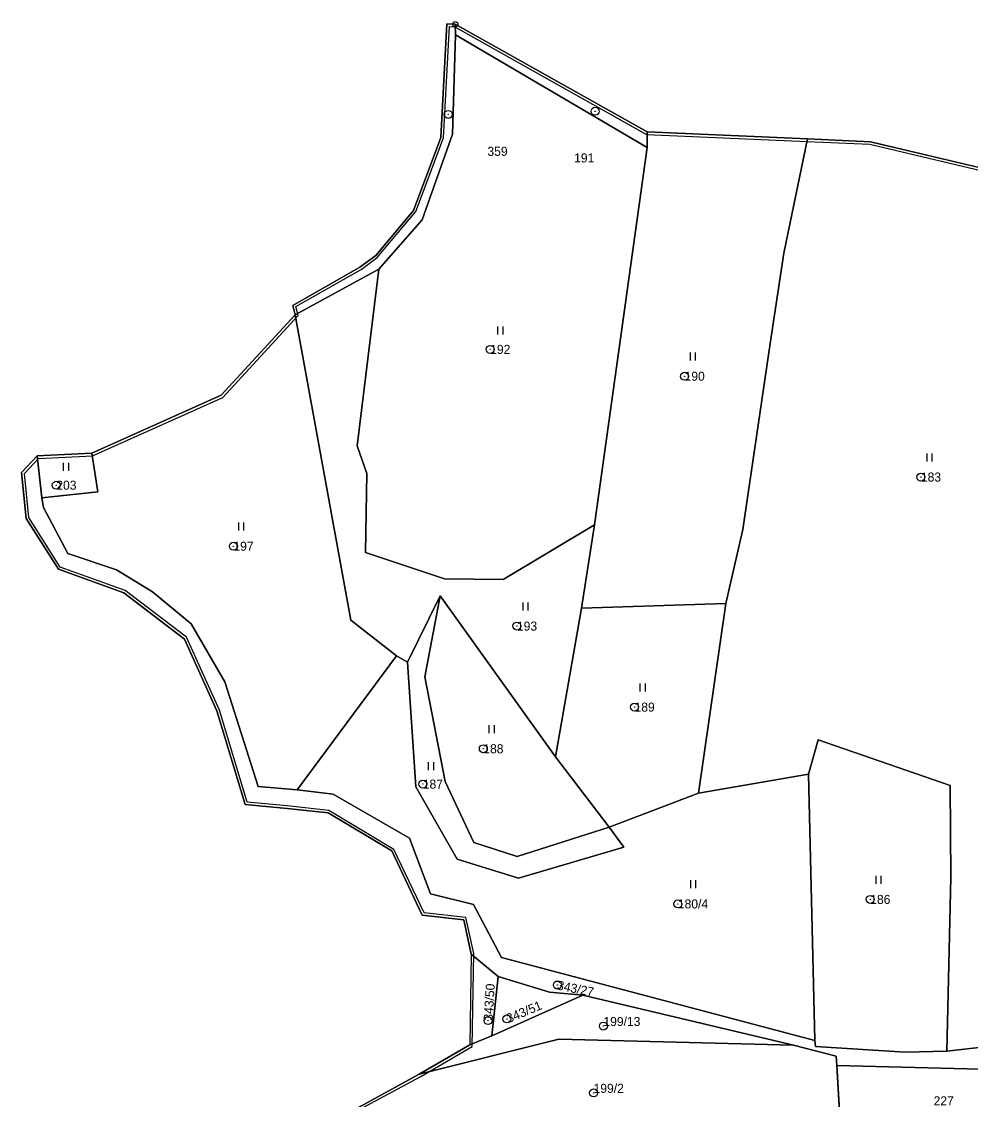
# Model space of a CAD drawing. Extents: x -652854 to -650068, y -1097661 to -1095417.
# Drawn here: x -651244.8 to -651066.4, y -1095861.8 to -1095659.2 of the extents above; entities that cross this region are included whole.
import ezdxf

# ---------------------------------------------------------------- set-up
doc = ezdxf.new("R2010")
doc.units = 0
for name, color, linetype in [('Definiční body parcel', 7, 'Continuous'), ('Geodetické body', 7, 'Continuous'), ('Hranice obcí', 7, 'Continuous'), ('Hranice parcel', 7, 'Continuous'), ('Obvody jako plochy', 7, 'Continuous'), ('Ostatní hranice', 7, 'Continuous'), ('Parcelní čísla', 7, 'Continuous'), ('Prvky pro prodl_ par_ č_', 7, 'Continuous'), ('Značky kultur', 7, 'Continuous')]:
    doc.layers.add(name, color=color, linetype=linetype)

msp = doc.modelspace()

# ---------------------------------------------------------------- linework, layer by layer
at = {"layer": 'Definiční body parcel'}
for centre, radius in [((-651164.58, -1095676.69), 0.75), ((-651164.58, -1095676.69), 0.0327), ((-651136.98, -1095676.09), 0.75), ((-651136.98, -1095676.09), 0.0327), ((-651156.7, -1095720.83), 0.75), ((-651156.7, -1095720.83), 0.0327), ((-651120.17, -1095725.88), 0.75), ((-651120.17, -1095725.88), 0.0327), ((-651075.76, -1095744.82), 0.75), ((-651238.24, -1095746.35), 0.75), ((-651075.76, -1095744.82), 0.0327), ((-651238.24, -1095746.35), 0.0327), ((-651204.96, -1095757.82), 0.75), ((-651204.96, -1095757.82), 0.0327), ((-651151.67, -1095772.83), 0.75), ((-651151.67, -1095772.83), 0.0327), ((-651129.57, -1095788.05), 0.75), ((-651129.57, -1095788.05), 0.0327), ((-651157.99, -1095795.88), 0.75), ((-651157.99, -1095795.88), 0.0327), ((-651169.36, -1095802.52), 0.75), ((-651169.36, -1095802.52), 0.0327), ((-651121.43, -1095825.03), 0.75), ((-651121.43, -1095825.03), 0.0327), ((-651085.28, -1095824.19), 0.75), ((-651085.28, -1095824.19), 0.0327), ((-651144.06, -1095840.27), 0.75), ((-651144.06, -1095840.27), 0.0327), ((-651157.1, -1095846.95), 0.75), ((-651157.1, -1095846.95), 0.0327), ((-651153.55, -1095846.64), 0.75), ((-651153.55, -1095846.64), 0.0327), ((-651135.42, -1095847.98), 0.75), ((-651135.42, -1095847.98), 0.0327), ((-651137.27, -1095860.54), 0.75), ((-651137.27, -1095860.54), 0.0327)]:
    msp.add_circle(centre, radius, dxfattribs=at)
at = {"layer": 'Geodetické body'}
for radius in [0.5, 0.001]:
    msp.add_circle((-651163.27, -1095659.73), radius, dxfattribs=at)
at = {"layer": 'Hranice obcí'}
for p, q in [((-651165.95, -1095681.01), (-651164.84, -1095659.68)), ((-651164.84, -1095659.68), (-651163.27, -1095659.73)), ((-651163.27, -1095659.73), (-651127.2, -1095679.95)), ((-651171.1, -1095694.72), (-651165.95, -1095681.01)), ((-651127.2, -1095679.95), (-651097.08, -1095681.29)), ((-651097.08, -1095681.29), (-651085.24, -1095681.81)), ((-651085.24, -1095681.81), (-651060.33, -1095687.71)), ((-651178.22, -1095703.17), (-651171.1, -1095694.72)), ((-651181.22, -1095705.41), (-651178.22, -1095703.17)), ((-651193.76, -1095712.57), (-651181.22, -1095705.41)), ((-651193.34, -1095714.35), (-651193.76, -1095712.57)), ((-651207.25, -1095729.45), (-651193.34, -1095714.35)), ((-651231.54, -1095740.33), (-651207.25, -1095729.45)), ((-651244.77, -1095743.96), (-651241.84, -1095740.85)), ((-651241.84, -1095740.85), (-651231.54, -1095740.33)), ((-651243.9, -1095752.59), (-651244.77, -1095743.96)), ((-651237.83, -1095762.16), (-651243.9, -1095752.59)), ((-651225.54, -1095766.59), (-651237.83, -1095762.16)), ((-651214.13, -1095775.29), (-651225.54, -1095766.59)), ((-651208.05, -1095788.78), (-651214.13, -1095775.29)), ((-651202.75, -1095806.38), (-651208.05, -1095788.78)), ((-651194.85, -1095807.11), (-651202.75, -1095806.38)), ((-651187.17, -1095807.94), (-651194.85, -1095807.11)), ((-651175.2, -1095815.09), (-651187.17, -1095807.94)), ((-651169.48, -1095827.15), (-651175.2, -1095815.09)), ((-651161.68, -1095828.05), (-651169.48, -1095827.15)), ((-651160.28, -1095834.46), (-651161.68, -1095828.05)), ((-651160.28, -1095834.46), (-651160.53, -1095851.53)), ((-651170.03, -1095857.03), (-651160.53, -1095851.53)), ((-651182.24, -1095863.72), (-651170.03, -1095857.03))]:
    msp.add_line(p, q, dxfattribs=at)
at = {"layer": 'Hranice parcel'}
for p, q in [((-651163.27, -1095659.73), (-651163.25, -1095661.73)), ((-651163.25, -1095661.73), (-651163.78, -1095680.37)), ((-651163.25, -1095661.73), (-651127.23, -1095682.88)), ((-651163.78, -1095680.37), (-651169.48, -1095696.47)), ((-651127.23, -1095682.88), (-651127.2, -1095679.95)), ((-651101.52, -1095702.76), (-651097.08, -1095681.29)), ((-651127.23, -1095682.88), (-651137.08, -1095753.83)), ((-651169.48, -1095696.47), (-651177.62, -1095705.76)), ((-651104.09, -1095719.7), (-651101.52, -1095702.76)), ((-651177.62, -1095705.76), (-651193.34, -1095714.35)), ((-651177.62, -1095705.76), (-651181.69, -1095738.94)), ((-651193.34, -1095714.35), (-651182.87, -1095771.73)), ((-651109.22, -1095754.65), (-651104.09, -1095719.7)), ((-651181.69, -1095738.94), (-651179.89, -1095744.15)), ((-651241.84, -1095740.85), (-651240.93, -1095748.75)), ((-651230.42, -1095747.57), (-651231.54, -1095740.33)), ((-651179.89, -1095744.15), (-651180.15, -1095759.02)), ((-651240.93, -1095748.75), (-651230.42, -1095747.57)), ((-651240.93, -1095748.75), (-651240.67, -1095750.53)), ((-651240.67, -1095750.53), (-651236.07, -1095759.2)), ((-651154.26, -1095764.1), (-651137.08, -1095753.83)), ((-651137.08, -1095753.83), (-651139.55, -1095769.48)), ((-651112.39, -1095768.57), (-651109.22, -1095754.65)), ((-651236.07, -1095759.2), (-651226.94, -1095762.27)), ((-651180.15, -1095759.02), (-651165.27, -1095763.93)), ((-651226.94, -1095762.27), (-651220.14, -1095766.41)), ((-651165.27, -1095763.93), (-651154.26, -1095764.1)), ((-651220.14, -1095766.41), (-651212.91, -1095772.43)), ((-651166.12, -1095767.15), (-651172.24, -1095779.58)), ((-651166.12, -1095767.15), (-651169.01, -1095782.37)), ((-651144.45, -1095797.37), (-651166.12, -1095767.15)), ((-651139.55, -1095769.48), (-651144.45, -1095797.37)), ((-651139.55, -1095769.48), (-651112.39, -1095768.57)), ((-651117.53, -1095804.25), (-651112.39, -1095768.57)), ((-651212.91, -1095772.43), (-651206.57, -1095783.31)), ((-651182.87, -1095771.73), (-651174.28, -1095778.39)), ((-651174.28, -1095778.39), (-651192.98, -1095803.61)), ((-651174.28, -1095778.39), (-651172.24, -1095779.58)), ((-651172.24, -1095779.58), (-651170.68, -1095803.06)), ((-651169.01, -1095782.37), (-651165.15, -1095802.04)), ((-651206.57, -1095783.31), (-651200.29, -1095802.99)), ((-651096.89, -1095800.65), (-651095.09, -1095794.17)), ((-651095.09, -1095794.17), (-651070.25, -1095802.81)), ((-651134.33, -1095810.62), (-651144.45, -1095797.37)), ((-651117.53, -1095804.25), (-651096.89, -1095800.65)), ((-651096.89, -1095800.65), (-651095.71, -1095850.7)), ((-651165.15, -1095802.04), (-651159.77, -1095813.5)), ((-651070.25, -1095802.81), (-651070.13, -1095820.09)), ((-651200.29, -1095802.99), (-651192.98, -1095803.61)), ((-651192.98, -1095803.61), (-651186.19, -1095804.38)), ((-651186.19, -1095804.38), (-651171.85, -1095812.66)), ((-651170.68, -1095803.06), (-651162.88, -1095816.62)), ((-651134.33, -1095810.62), (-651117.53, -1095804.25)), ((-651151.61, -1095816.14), (-651134.33, -1095810.62)), ((-651131.57, -1095814.34), (-651134.33, -1095810.62)), ((-651171.85, -1095812.66), (-651167.94, -1095823.12)), ((-651159.77, -1095813.5), (-651151.61, -1095816.14)), ((-651151.37, -1095820.22), (-651131.57, -1095814.34)), ((-651162.88, -1095816.62), (-651151.37, -1095820.22)), ((-651070.13, -1095820.09), (-651070.86, -1095852.7)), ((-651167.94, -1095823.12), (-651159.86, -1095825.12)), ((-651159.86, -1095825.12), (-651154.58, -1095835.1)), ((-651155.23, -1095838.66), (-651160.28, -1095834.46)), ((-651154.58, -1095835.1), (-651095.71, -1095850.7)), ((-651155.23, -1095838.66), (-651156.42, -1095849.83)), ((-651145.53, -1095841.59), (-651155.23, -1095838.66)), ((-651156.42, -1095849.83), (-651139.31, -1095842.16)), ((-651139.31, -1095842.16), (-651145.53, -1095841.59)), ((-651139.31, -1095842.16), (-651099.73, -1095851.59)), ((-651143.81, -1095850.45), (-651170.03, -1095857.03)), ((-651160.53, -1095851.53), (-651156.42, -1095849.83)), ((-651099.73, -1095851.59), (-651143.81, -1095850.45)), ((-651095.71, -1095850.7), (-651095.54, -1095851.8)), ((-651099.73, -1095851.59), (-651091.66, -1095853.64)), ((-651095.54, -1095851.8), (-651078.71, -1095852.88)), ((-651078.71, -1095852.88), (-651070.86, -1095852.7)), ((-651070.86, -1095852.7), (-651063.2, -1095851.8)), ((-651091.53, -1095855.39), (-651091.66, -1095853.64)), ((-651091.53, -1095855.39), (-651054.94, -1095856.32)), ((-651090.63, -1095871.34), (-651091.53, -1095855.39))]:
    msp.add_line(p, q, dxfattribs=at)
at = {"layer": 'Obvody jako plochy'}
for points in [[(-651163.78, -1095680.37), (-651163.25, -1095661.73), (-651163.27, -1095659.73), (-651164.84, -1095659.68), (-651165.95, -1095681.01), (-651171.1, -1095694.72), (-651178.22, -1095703.17), (-651181.22, -1095705.41), (-651193.76, -1095712.57), (-651193.34, -1095714.35), (-651177.62, -1095705.76), (-651169.48, -1095696.47)], [(-651163.25, -1095661.73), (-651127.23, -1095682.88), (-651127.2, -1095679.95), (-651163.27, -1095659.73)], [(-651163.78, -1095680.37), (-651169.48, -1095696.47), (-651177.62, -1095705.76), (-651181.69, -1095738.94), (-651179.89, -1095744.15), (-651180.15, -1095759.02), (-651165.27, -1095763.93), (-651154.26, -1095764.1), (-651137.08, -1095753.83), (-651127.23, -1095682.88), (-651163.25, -1095661.73)], [(-651112.39, -1095768.57), (-651109.22, -1095754.65), (-651104.09, -1095719.7), (-651101.52, -1095702.76), (-651097.08, -1095681.29), (-651127.2, -1095679.95), (-651127.23, -1095682.88), (-651137.08, -1095753.83), (-651139.55, -1095769.48)], [(-651112.39, -1095768.57), (-651117.53, -1095804.25), (-651096.89, -1095800.65), (-651095.09, -1095794.17), (-651070.25, -1095802.81), (-651070.13, -1095820.09), (-651070.86, -1095852.7), (-651063.2, -1095851.8), (-651060.77, -1095828.02), (-651058.73, -1095802.33), (-651055.01, -1095780.49), (-651049.97, -1095744.99), (-651047.21, -1095731.45), (-651038.08, -1095692.34), (-651060.33, -1095687.71), (-651085.24, -1095681.81), (-651097.08, -1095681.29), (-651101.52, -1095702.76), (-651104.09, -1095719.7), (-651109.22, -1095754.65)], [(-651177.62, -1095705.76), (-651193.34, -1095714.35), (-651182.87, -1095771.73), (-651174.28, -1095778.39), (-651172.24, -1095779.58), (-651166.12, -1095767.15), (-651144.45, -1095797.37), (-651139.55, -1095769.48), (-651137.08, -1095753.83), (-651154.26, -1095764.1), (-651165.27, -1095763.93), (-651180.15, -1095759.02), (-651179.89, -1095744.15), (-651181.69, -1095738.94)], [(-651207.25, -1095729.45), (-651231.54, -1095740.33), (-651230.42, -1095747.57), (-651240.93, -1095748.75), (-651240.67, -1095750.53), (-651236.07, -1095759.2), (-651226.94, -1095762.27), (-651220.14, -1095766.41), (-651212.91, -1095772.43), (-651206.57, -1095783.31), (-651200.29, -1095802.99), (-651192.98, -1095803.61), (-651174.28, -1095778.39), (-651182.87, -1095771.73), (-651193.34, -1095714.35)], [(-651241.84, -1095740.85), (-651240.93, -1095748.75), (-651230.42, -1095747.57), (-651231.54, -1095740.33)], [(-651172.24, -1095779.58), (-651170.68, -1095803.06), (-651162.88, -1095816.62), (-651151.37, -1095820.22), (-651131.57, -1095814.34), (-651134.33, -1095810.62), (-651151.61, -1095816.14), (-651159.77, -1095813.5), (-651165.15, -1095802.04), (-651169.01, -1095782.37), (-651166.12, -1095767.15)], [(-651159.77, -1095813.5), (-651151.61, -1095816.14), (-651134.33, -1095810.62), (-651144.45, -1095797.37), (-651166.12, -1095767.15), (-651169.01, -1095782.37), (-651165.15, -1095802.04)], [(-651139.55, -1095769.48), (-651144.45, -1095797.37), (-651134.33, -1095810.62), (-651117.53, -1095804.25), (-651112.39, -1095768.57)], [(-651186.19, -1095804.38), (-651171.85, -1095812.66), (-651167.94, -1095823.12), (-651159.86, -1095825.12), (-651154.58, -1095835.1), (-651095.71, -1095850.7), (-651096.89, -1095800.65), (-651117.53, -1095804.25), (-651134.33, -1095810.62), (-651131.57, -1095814.34), (-651151.37, -1095820.22), (-651162.88, -1095816.62), (-651170.68, -1095803.06), (-651172.24, -1095779.58), (-651174.28, -1095778.39), (-651192.98, -1095803.61)], [(-651095.71, -1095850.7), (-651095.54, -1095851.8), (-651078.71, -1095852.88), (-651070.86, -1095852.7), (-651070.13, -1095820.09), (-651070.25, -1095802.81), (-651095.09, -1095794.17), (-651096.89, -1095800.65)], [(-651160.53, -1095851.53), (-651156.42, -1095849.83), (-651155.23, -1095838.66), (-651160.28, -1095834.46)], [(-651156.42, -1095849.83), (-651139.31, -1095842.16), (-651145.53, -1095841.59), (-651155.23, -1095838.66)], [(-651160.53, -1095851.53), (-651170.03, -1095857.03), (-651143.81, -1095850.45), (-651099.73, -1095851.59), (-651139.31, -1095842.16), (-651156.42, -1095849.83)], [(-651124.53, -1095872.94), (-651106.05, -1095871.75), (-651093.24, -1095871.75), (-651090.63, -1095871.34), (-651091.53, -1095855.39), (-651091.66, -1095853.64), (-651099.73, -1095851.59), (-651143.81, -1095850.45), (-651170.03, -1095857.03), (-651182.24, -1095863.72), (-651181.83, -1095868.33), (-651181.14, -1095876.14)], [(-651054.94, -1095856.32), (-651091.53, -1095855.39), (-651090.63, -1095871.34), (-651054.66, -1095867.16)]]:
    msp.add_lwpolyline(points, close=True, dxfattribs=at)
msp.add_lwpolyline([(-651063.2, -1095851.8), (-651070.86, -1095852.7), (-651078.71, -1095852.88), (-651095.54, -1095851.8), (-651095.71, -1095850.7), (-651154.58, -1095835.1), (-651159.86, -1095825.12), (-651167.94, -1095823.12), (-651171.85, -1095812.66), (-651186.19, -1095804.38), (-651192.98, -1095803.61), (-651200.29, -1095802.99), (-651206.57, -1095783.31), (-651212.91, -1095772.43), (-651220.14, -1095766.41), (-651226.94, -1095762.27), (-651236.07, -1095759.2), (-651240.67, -1095750.53), (-651240.93, -1095748.75), (-651241.84, -1095740.85), (-651244.77, -1095743.96), (-651243.9, -1095752.59), (-651237.83, -1095762.16), (-651225.54, -1095766.59), (-651214.13, -1095775.29), (-651208.05, -1095788.78), (-651202.75, -1095806.38), (-651194.85, -1095807.11), (-651187.17, -1095807.94), (-651175.2, -1095815.09), (-651169.48, -1095827.15), (-651161.68, -1095828.05), (-651160.28, -1095834.46), (-651155.23, -1095838.66), (-651145.53, -1095841.59), (-651139.31, -1095842.16), (-651099.73, -1095851.59), (-651091.66, -1095853.64), (-651091.53, -1095855.39), (-651054.94, -1095856.32)], dxfattribs=at)
at = {"layer": 'Ostatní hranice'}
for p, q in [((-651165.46, -1095681.11), (-651164.37, -1095660.18)), ((-651164.37, -1095660.18), (-651163.36, -1095660.22)), ((-651163.36, -1095660.22), (-651127.31, -1095680.43)), ((-651170.67, -1095694.95), (-651165.46, -1095681.11)), ((-651127.31, -1095680.43), (-651097.1, -1095681.77)), ((-651097.1, -1095681.77), (-651085.33, -1095682.28)), ((-651085.33, -1095682.28), (-651060.46, -1095688.18)), ((-651177.91, -1095703.55), (-651170.67, -1095694.95)), ((-651180.95, -1095705.82), (-651177.91, -1095703.55)), ((-651193.22, -1095712.79), (-651180.95, -1095705.82)), ((-651192.8, -1095714.49), (-651193.22, -1095712.79)), ((-651206.96, -1095729.87), (-651192.8, -1095714.49)), ((-651231.41, -1095740.82), (-651206.96, -1095729.87)), ((-651244.24, -1095744.13), (-651241.61, -1095741.35)), ((-651241.61, -1095741.35), (-651231.41, -1095740.82)), ((-651243.43, -1095752.4), (-651244.24, -1095744.13)), ((-651237.54, -1095761.74), (-651243.43, -1095752.4)), ((-651225.29, -1095766.15), (-651237.54, -1095761.74)), ((-651213.76, -1095774.94), (-651225.29, -1095766.15)), ((-651207.56, -1095788.64), (-651213.76, -1095774.94)), ((-651202.36, -1095805.9), (-651207.56, -1095788.64)), ((-651194.84, -1095806.6), (-651202.36, -1095805.9)), ((-651187, -1095807.46), (-651194.84, -1095806.6)), ((-651174.78, -1095814.81), (-651187, -1095807.46)), ((-651169.12, -1095826.73), (-651174.78, -1095814.81)), ((-651161.27, -1095827.6), (-651169.12, -1095826.73)), ((-651159.78, -1095834.37), (-651161.27, -1095827.6)), ((-651160.06, -1095851.85), (-651159.78, -1095834.37)), ((-651169.75, -1095857.45), (-651160.06, -1095851.85)), ((-651181.78, -1095863.92), (-651169.75, -1095857.45))]:
    msp.add_line(p, q, dxfattribs=at)
at = {"layer": 'Značky kultur'}
for p, q in [((-651155.307, -1095716.525), (-651155.307, -1095718.025)), ((-651154.285, -1095718.025), (-651154.285, -1095716.525)), ((-651119.147, -1095721.445), (-651119.147, -1095722.945)), ((-651118.125, -1095722.945), (-651118.125, -1095721.445)), ((-651074.657, -1095740.385), (-651074.657, -1095741.885)), ((-651073.635, -1095741.885), (-651073.635, -1095740.385)), ((-651236.927, -1095742.135), (-651236.927, -1095743.635)), ((-651235.905, -1095743.635), (-651235.905, -1095742.135)), ((-651203.997, -1095753.385), (-651203.997, -1095754.885)), ((-651202.975, -1095754.885), (-651202.975, -1095753.385)), ((-651150.587, -1095768.395), (-651150.587, -1095769.895)), ((-651149.565, -1095769.895), (-651149.565, -1095768.395)), ((-651128.547, -1095783.615), (-651128.547, -1095785.115)), ((-651127.525, -1095785.115), (-651127.525, -1095783.615)), ((-651156.937, -1095791.445), (-651156.937, -1095792.945)), ((-651155.915, -1095792.945), (-651155.915, -1095791.445)), ((-651168.327, -1095798.415), (-651168.327, -1095799.915)), ((-651167.305, -1095799.915), (-651167.305, -1095798.415)), ((-651119.077, -1095820.595), (-651119.077, -1095822.095)), ((-651118.055, -1095822.095), (-651118.055, -1095820.595)), ((-651084.257, -1095819.755), (-651084.257, -1095821.255)), ((-651083.235, -1095821.255), (-651083.235, -1095819.755))]:
    msp.add_line(p, q, dxfattribs=at)

# ---------------------------------------------------------------- texts
at = {"layer": 'Parcelní čísla'}
for s, height, p in [('359', 0.1, (-651164.58, -1095676.69)), ('191', 0.1, (-651136.98, -1095676.09)), ('192', 1.7, (-651156.7, -1095721.68)), ('190', 1.7, (-651120.17, -1095726.73)), ('183', 1.7, (-651075.76, -1095745.67)), ('203', 1.7, (-651238.24, -1095747.2)), ('197', 1.7, (-651204.96, -1095758.67)), ('193', 1.7, (-651151.67, -1095773.68)), ('189', 1.7, (-651129.57, -1095788.9)), ('188', 1.7, (-651157.99, -1095796.73)), ('187', 1.7, (-651169.36, -1095803.37)), ('180/4', 1.7, (-651121.43, -1095825.88)), ('186', 1.7, (-651085.28, -1095825.04)), ('199/13', 1.7, (-651135.42, -1095847.98)), ('199/2', 1.7, (-651137.27, -1095860.54)), ('227', 1.7, (-651073.37, -1095862.89))]:
    msp.add_text(s, height=height, dxfattribs=at).set_placement(p)
for s, rotation, p in [('343/50', 86.382, (-651156.252, -1095847.004)), ('343/27', 348.687, (-651144.227, -1095841.103)), ('343/51', 22.617, (-651153.223, -1095847.425))]:
    msp.add_text(s, height=1.7, rotation=rotation, dxfattribs=at).set_placement(p)
at = {"layer": 'Prvky pro prodl_ par_ č_'}
for s, p in [('359', (-651157.22, -1095684.47)), ('191', (-651140.926, -1095685.71))]:
    msp.add_text(s, height=1.7, dxfattribs=at).set_placement(p)

doc.saveas('drawing.dxf')
